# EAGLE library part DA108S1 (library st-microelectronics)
DIODE ARRAY (ASD)
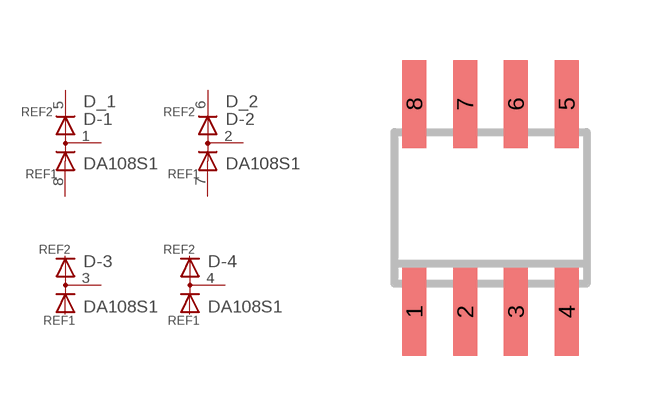
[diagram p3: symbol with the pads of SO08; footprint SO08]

Designator prefix D; gates _1=REF -1=D-1 _2=REF -2=D-1 -3=D-2-1 -4=D-2-1

## DA108S1 (MF: Arrow Electronics; MPN: DA108S1; OC_FARNELL: 9802215; OC_NEWARK: 89K0513)  [SO08]
1  -1:K  pas
2  -2:K  pas
3  -3:K  pas
4  -4:K  pas
5  _1:REF2  pas
6  _2:REF2  pas
7  _2:REF1  pas
8  _1:REF1  pas

## Footprint SO08 (pad centres in mm)
SMALL OUTLINE INTEGRATED CIRCUIT body 3.9 mm/JEDEC MS-012AA
smd 0.6 x 2.2: 1 -1.905,-2.6; 2 -0.635,-2.6; 3 0.635,-2.6; 4 1.905,-2.6; 5 1.905,2.6; 6 0.635,2.6; 7 -0.635,2.6; 8 -1.905,2.6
